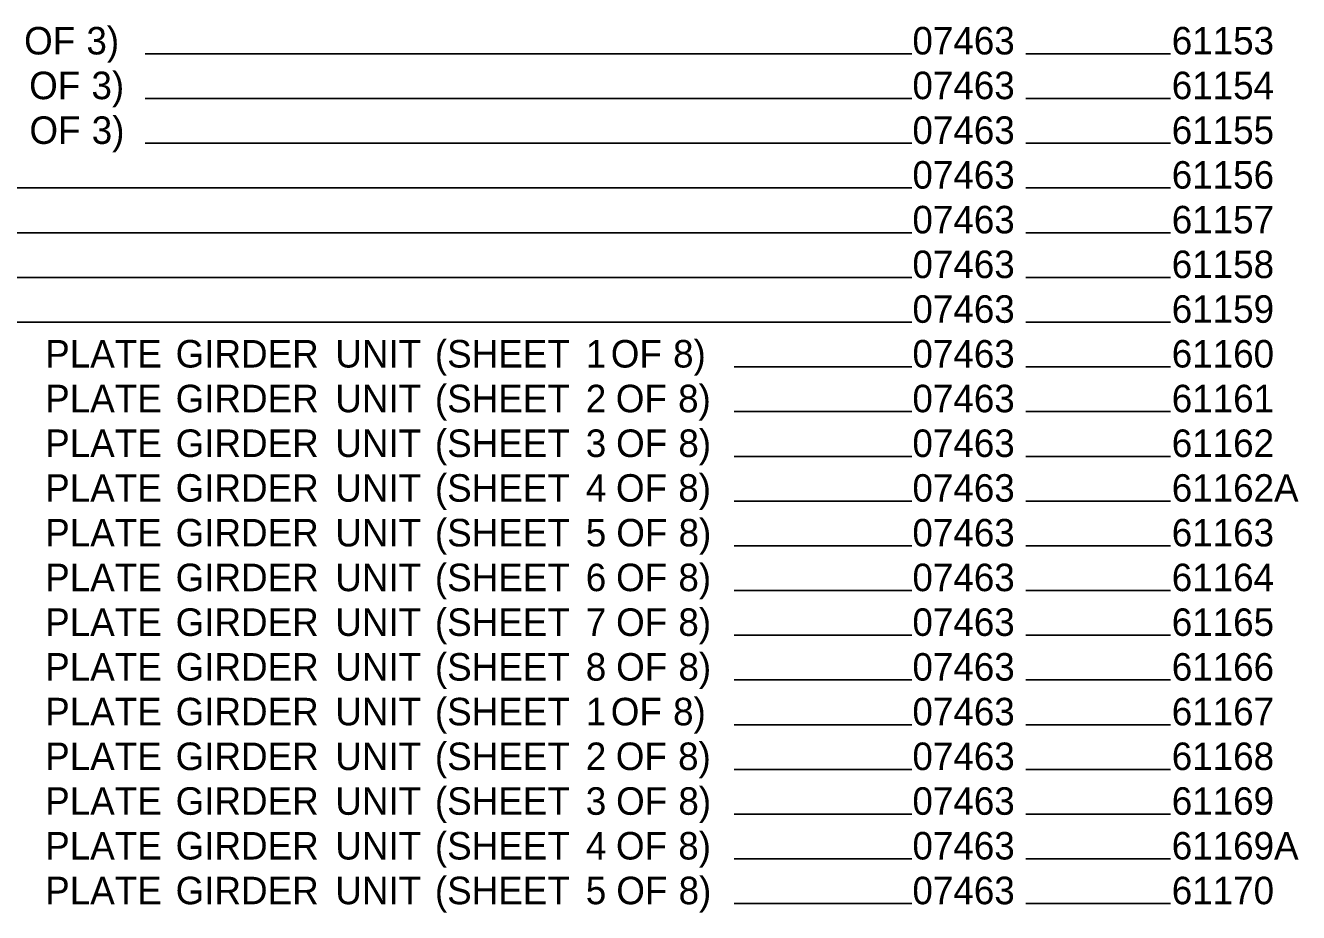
# Model space of a CAD drawing. Extents: x 2 to 32.9, y 0.7 to 21.4.
# Drawn here: x 8.57 to 15.85, y 6.1 to 11.17 of the extents above; entities that cross this region are included whole.
import ezdxf

# ---------------------------------------------------------------- set-up
doc = ezdxf.new("R2010")
doc.units = 0
doc.layers.add('Default', color=7, linetype='Continuous')

msp = doc.modelspace()

# ---------------------------------------------------------------- linework, layer by layer
at = {"layer": 'Default'}
for p, q in [((9.2517, 11.0032), (13.6355, 11.0032)), ((14.286, 11.0032), (15.1138, 11.0032)), ((9.2517, 10.7476), (13.6355, 10.7476)), ((14.286, 10.7476), (15.1138, 10.7476)), ((9.2517, 10.492), (13.6355, 10.492)), ((14.286, 10.492), (15.1138, 10.492)), ((7.9777, 10.2364), (13.6355, 10.2364)), ((14.286, 10.2364), (15.1138, 10.2364)), ((7.993, 9.9808), (13.6355, 9.9808)), ((14.286, 9.9808), (15.1138, 9.9808)), ((7.9806, 9.7252), (13.6355, 9.7252)), ((14.286, 9.7252), (15.1138, 9.7252)), ((7.8234, 9.4696), (13.6355, 9.4696)), ((14.286, 9.4696), (15.1138, 9.4696)), ((12.6184, 9.214), (13.6355, 9.214)), ((14.286, 9.214), (15.1138, 9.214)), ((12.6184, 8.9584), (13.6355, 8.9584)), ((14.286, 8.9584), (15.1138, 8.9584)), ((12.6184, 8.7028), (13.6355, 8.7028)), ((14.286, 8.7028), (15.1138, 8.7028)), ((12.6184, 8.4473), (13.6355, 8.4473)), ((14.286, 8.4473), (15.1138, 8.4473)), ((12.6184, 8.1917), (13.6355, 8.1917)), ((14.286, 8.1917), (15.1138, 8.1917)), ((12.6184, 7.9361), (13.6355, 7.9361)), ((14.286, 7.9361), (15.1138, 7.9361)), ((12.6184, 7.6805), (13.6355, 7.6805)), ((14.286, 7.6805), (15.1138, 7.6805)), ((12.6184, 7.4249), (13.6355, 7.4249)), ((14.286, 7.4249), (15.1138, 7.4249)), ((12.6184, 7.1693), (13.6355, 7.1693)), ((14.286, 7.1693), (15.1138, 7.1693)), ((12.6184, 6.9137), (13.6355, 6.9137)), ((14.286, 6.9137), (15.1138, 6.9137)), ((12.6184, 6.6581), (13.6355, 6.6581)), ((14.286, 6.6581), (15.1138, 6.6581)), ((12.6184, 6.4025), (13.6355, 6.4025)), ((14.286, 6.4025), (15.1138, 6.4025)), ((12.6184, 6.1469), (13.6355, 6.1469)), ((14.286, 6.1469), (15.1138, 6.1469))]:
    msp.add_line(p, q, dxfattribs=at)

# ---------------------------------------------------------------- texts
for s, p in [(' OF', (8.5016, 10.9995)), (' OF', (8.5016, 10.9995)), (' 3)', (8.8578, 10.9995)), (' 3)', (8.8578, 10.9995)), ('07463', (13.6381, 10.9995)), ('07463', (13.6381, 10.9995)), ('61153', (15.1205, 10.9995)), ('61153', (15.1205, 10.9995)), (' OF', (8.5304, 10.7439)), (' OF', (8.5304, 10.7439)), (' 3)', (8.8865, 10.7439)), (' 3)', (8.8865, 10.7439)), ('07463', (13.6381, 10.7439)), ('07463', (13.6381, 10.7439)), ('61154', (15.1205, 10.7439)), ('61154', (15.1205, 10.7439)), (' OF', (8.532, 10.4883)), (' OF', (8.532, 10.4883)), (' 3)', (8.8882, 10.4883)), (' 3)', (8.8882, 10.4883)), ('07463', (13.6381, 10.4883)), ('07463', (13.6381, 10.4883)), ('61155', (15.1205, 10.4883)), ('61155', (15.1205, 10.4883)), ('07463', (13.6381, 10.2327)), ('07463', (13.6381, 10.2327)), ('61156', (15.1205, 10.2327)), ('61156', (15.1205, 10.2327)), ('07463', (13.6381, 9.9771)), ('07463', (13.6381, 9.9771)), ('61157', (15.1205, 9.9771)), ('61157', (15.1205, 9.9771)), ('07463', (13.6381, 9.7215)), ('07463', (13.6381, 9.7215)), ('61158', (15.1205, 9.7215)), ('61158', (15.1205, 9.7215)), ('07463', (13.6381, 9.466)), ('07463', (13.6381, 9.466)), ('61159', (15.1205, 9.466)), ('61159', (15.1205, 9.466)), (' PLATE', (8.6222, 9.2104)), (' PLATE', (8.6222, 9.2104)), (' GIRDER', (9.3677, 9.2104)), (' GIRDER', (9.3677, 9.2104)), (' UNIT', (10.2805, 9.2104)), (' UNIT', (10.2805, 9.2104)), (' (SHEET', (10.8499, 9.2104)), (' (SHEET', (10.8499, 9.2104)), (' 1', (11.7124, 9.2104)), (' 1', (11.7124, 9.2104)), (' OF', (11.8552, 9.2104)), (' OF', (11.8552, 9.2104)), (' 8)', (12.2114, 9.2104)), (' 8)', (12.2114, 9.2104)), ('07463', (13.6381, 9.2104)), ('07463', (13.6381, 9.2104)), ('61160', (15.1205, 9.2104)), ('61160', (15.1205, 9.2104)), (' PLATE', (8.6222, 8.9548)), (' PLATE', (8.6222, 8.9548)), (' GIRDER', (9.3677, 8.9548)), (' GIRDER', (9.3677, 8.9548)), (' UNIT', (10.2805, 8.9548)), (' UNIT', (10.2805, 8.9548)), (' (SHEET', (10.8499, 8.9548)), (' (SHEET', (10.8499, 8.9548)), (' 2', (11.7124, 8.9548)), (' 2', (11.7124, 8.9548)), (' OF', (11.884, 8.9548)), (' OF', (11.884, 8.9548)), (' 8)', (12.2401, 8.9548)), (' 8)', (12.2401, 8.9548)), ('07463', (13.6381, 8.9548)), ('07463', (13.6381, 8.9548)), ('61161', (15.1205, 8.9548)), ('61161', (15.1205, 8.9548)), (' PLATE', (8.6222, 8.6992)), (' PLATE', (8.6222, 8.6992)), (' GIRDER', (9.3677, 8.6992)), (' GIRDER', (9.3677, 8.6992)), (' UNIT', (10.2805, 8.6992)), (' UNIT', (10.2805, 8.6992)), (' (SHEET', (10.8499, 8.6992)), (' (SHEET', (10.8499, 8.6992)), (' 3', (11.7124, 8.6992)), (' 3', (11.7124, 8.6992)), (' OF', (11.8856, 8.6992)), (' OF', (11.8856, 8.6992)), (' 8)', (12.2418, 8.6992)), (' 8)', (12.2418, 8.6992)), ('07463', (13.6381, 8.6992)), ('07463', (13.6381, 8.6992)), ('61162', (15.1205, 8.6992)), ('61162', (15.1205, 8.6992)), (' PLATE', (8.6222, 8.4436)), (' PLATE', (8.6222, 8.4436)), (' GIRDER', (9.3677, 8.4436)), (' GIRDER', (9.3677, 8.4436)), (' UNIT', (10.2805, 8.4436)), (' UNIT', (10.2805, 8.4436)), (' (SHEET', (10.8499, 8.4436)), (' (SHEET', (10.8499, 8.4436)), (' 4', (11.7124, 8.4436)), (' 4', (11.7124, 8.4436)), (' OF', (11.8849, 8.4436)), (' OF', (11.8849, 8.4436)), (' 8)', (12.2411, 8.4436)), (' 8)', (12.2411, 8.4436)), ('07463', (13.6381, 8.4436)), ('07463', (13.6381, 8.4436)), ('61162A', (15.1205, 8.4436)), ('61162A', (15.1205, 8.4436)), (' PLATE', (8.6222, 8.188)), (' PLATE', (8.6222, 8.188)), (' GIRDER', (9.3677, 8.188)), (' GIRDER', (9.3677, 8.188)), (' UNIT', (10.2805, 8.188)), (' UNIT', (10.2805, 8.188)), (' (SHEET', (10.8499, 8.188)), (' (SHEET', (10.8499, 8.188)), (' 5', (11.7124, 8.188)), (' 5', (11.7124, 8.188)), (' OF', (11.8868, 8.188)), (' OF', (11.8868, 8.188)), (' 8)', (12.243, 8.188)), (' 8)', (12.243, 8.188)), ('07463', (13.6381, 8.188)), ('07463', (13.6381, 8.188)), ('61163', (15.1205, 8.188)), ('61163', (15.1205, 8.188)), (' PLATE', (8.6222, 7.9324)), (' PLATE', (8.6222, 7.9324)), (' GIRDER', (9.3677, 7.9324)), (' GIRDER', (9.3677, 7.9324)), (' UNIT', (10.2805, 7.9324)), (' UNIT', (10.2805, 7.9324)), (' (SHEET', (10.8499, 7.9324)), (' (SHEET', (10.8499, 7.9324)), (' 6', (11.7124, 7.9324)), (' 6', (11.7124, 7.9324)), (' OF', (11.8856, 7.9324)), (' OF', (11.8856, 7.9324)), (' 8)', (12.2418, 7.9324)), (' 8)', (12.2418, 7.9324)), ('07463', (13.6381, 7.9324)), ('07463', (13.6381, 7.9324)), ('61164', (15.1205, 7.9324)), ('61164', (15.1205, 7.9324)), (' PLATE', (8.6222, 7.6768)), (' PLATE', (8.6222, 7.6768)), (' GIRDER', (9.3677, 7.6768)), (' GIRDER', (9.3677, 7.6768)), (' UNIT', (10.2805, 7.6768)), (' UNIT', (10.2805, 7.6768)), (' (SHEET', (10.8499, 7.6768)), (' (SHEET', (10.8499, 7.6768)), (' 7', (11.7124, 7.6768)), (' 7', (11.7124, 7.6768)), (' OF', (11.8856, 7.6768)), (' OF', (11.8856, 7.6768)), (' 8)', (12.2418, 7.6768)), (' 8)', (12.2418, 7.6768)), ('07463', (13.6381, 7.6768)), ('07463', (13.6381, 7.6768)), ('61165', (15.1205, 7.6768)), ('61165', (15.1205, 7.6768)), (' PLATE', (8.6222, 7.4212)), (' PLATE', (8.6222, 7.4212)), (' GIRDER', (9.3677, 7.4212)), (' GIRDER', (9.3677, 7.4212)), (' UNIT', (10.2805, 7.4212)), (' UNIT', (10.2805, 7.4212)), (' (SHEET', (10.8499, 7.4212)), (' (SHEET', (10.8499, 7.4212)), (' 8', (11.7124, 7.4212)), (' 8', (11.7124, 7.4212)), (' OF', (11.8859, 7.4212)), (' OF', (11.8859, 7.4212)), (' 8)', (12.2421, 7.4212)), (' 8)', (12.2421, 7.4212)), ('07463', (13.6381, 7.4212)), ('07463', (13.6381, 7.4212)), ('61166', (15.1205, 7.4212)), ('61166', (15.1205, 7.4212)), (' PLATE', (8.6222, 7.1656)), (' PLATE', (8.6222, 7.1656)), (' GIRDER', (9.3677, 7.1656)), (' GIRDER', (9.3677, 7.1656)), (' UNIT', (10.2805, 7.1656)), (' UNIT', (10.2805, 7.1656)), (' (SHEET', (10.8499, 7.1656)), (' (SHEET', (10.8499, 7.1656)), (' 1', (11.7124, 7.1656)), (' 1', (11.7124, 7.1656)), (' OF', (11.8552, 7.1656)), (' OF', (11.8552, 7.1656)), (' 8)', (12.2114, 7.1656)), (' 8)', (12.2114, 7.1656)), ('07463', (13.6381, 7.1656)), ('07463', (13.6381, 7.1656)), ('61167', (15.1205, 7.1656)), ('61167', (15.1205, 7.1656)), (' PLATE', (8.6222, 6.9101)), (' PLATE', (8.6222, 6.9101)), (' GIRDER', (9.3677, 6.9101)), (' GIRDER', (9.3677, 6.9101)), (' UNIT', (10.2805, 6.9101)), (' UNIT', (10.2805, 6.9101)), (' (SHEET', (10.8499, 6.9101)), (' (SHEET', (10.8499, 6.9101)), (' 2', (11.7124, 6.9101)), (' 2', (11.7124, 6.9101)), (' OF', (11.884, 6.9101)), (' OF', (11.884, 6.9101)), (' 8)', (12.2401, 6.9101)), (' 8)', (12.2401, 6.9101)), ('07463', (13.6381, 6.9101)), ('07463', (13.6381, 6.9101)), ('61168', (15.1205, 6.9101)), ('61168', (15.1205, 6.9101)), (' PLATE', (8.6222, 6.6545)), (' PLATE', (8.6222, 6.6545)), (' GIRDER', (9.3677, 6.6545)), (' GIRDER', (9.3677, 6.6545)), (' UNIT', (10.2805, 6.6545)), (' UNIT', (10.2805, 6.6545)), (' (SHEET', (10.8499, 6.6545)), (' (SHEET', (10.8499, 6.6545)), (' 3', (11.7124, 6.6545)), (' 3', (11.7124, 6.6545)), (' OF', (11.8856, 6.6545)), (' OF', (11.8856, 6.6545)), (' 8)', (12.2418, 6.6545)), (' 8)', (12.2418, 6.6545)), ('07463', (13.6381, 6.6545)), ('07463', (13.6381, 6.6545)), ('61169', (15.1205, 6.6545)), ('61169', (15.1205, 6.6545)), (' PLATE', (8.6222, 6.3989)), (' PLATE', (8.6222, 6.3989)), (' GIRDER', (9.3677, 6.3989)), (' GIRDER', (9.3677, 6.3989)), (' UNIT', (10.2805, 6.3989)), (' UNIT', (10.2805, 6.3989)), (' (SHEET', (10.8499, 6.3989)), (' (SHEET', (10.8499, 6.3989)), (' 4', (11.7124, 6.3989)), (' 4', (11.7124, 6.3989)), (' OF', (11.8849, 6.3989)), (' OF', (11.8849, 6.3989)), (' 8)', (12.2411, 6.3989)), (' 8)', (12.2411, 6.3989)), ('07463', (13.6381, 6.3989)), ('07463', (13.6381, 6.3989)), ('61169A', (15.1205, 6.3989)), ('61169A', (15.1205, 6.3989)), (' PLATE', (8.6222, 6.1433)), (' PLATE', (8.6222, 6.1433)), (' GIRDER', (9.3677, 6.1433)), (' GIRDER', (9.3677, 6.1433)), (' UNIT', (10.2805, 6.1433)), (' UNIT', (10.2805, 6.1433)), (' (SHEET', (10.8499, 6.1433)), (' (SHEET', (10.8499, 6.1433)), (' 5', (11.7124, 6.1433)), (' 5', (11.7124, 6.1433)), (' OF', (11.8868, 6.1433)), (' OF', (11.8868, 6.1433)), (' 8)', (12.243, 6.1433)), (' 8)', (12.243, 6.1433)), ('07463', (13.6381, 6.1433)), ('07463', (13.6381, 6.1433)), ('61170', (15.1205, 6.1433)), ('61170', (15.1205, 6.1433))]:
    msp.add_text(s, height=0.15729, dxfattribs=at).set_placement(p)

doc.saveas('drawing.dxf')
